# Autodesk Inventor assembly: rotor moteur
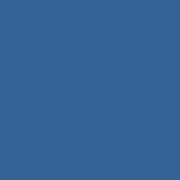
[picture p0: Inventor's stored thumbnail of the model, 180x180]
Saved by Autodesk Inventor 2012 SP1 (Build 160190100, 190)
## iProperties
Created: 2011-01
Part Number: rotor moteur
Document SubType Name: Assembly
Designer: eric
Mass: 15.8906 g
Surface Area: 104.881 cm^2
Volume: 15.8906 cm^3
Density: 1 g/cm^3
Author: eric
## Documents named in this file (5)
- D:\Cours\Inventor salle SI\chariot_de_golf_2008\chariot_de_golf_trolem\rotor moteur.iam
- D:\Cours\Inventor salle SI\chariot_de_golf_2008\chariot_de_golf_trolem\12Vis-sans-fin_Defaut.ipt
- D:\Cours\Inventor salle SI\chariot_de_golf_2008\chariot_de_golf_trolem\12manchon_accouplement_Defaut.ipt
- D:\Cours\Inventor salle SI\chariot_de_golf_2008\chariot_de_golf_trolem\12croix_elastique_Defaut.ipt
- D:\Cours\Inventor salle SI\chariot_de_golf_2008\chariot_de_golf_trolem\12axe_moteur_Defaut.ipt
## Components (5 placed, 4 different names)
1. 12Vis-sans-fin_Defaut:1
2. 12croix_elastique_Defaut:1
3. 12manchon_accouplement_Defaut:2
4. 12axe_moteur_Defaut:1
5. 12manchon_accouplement_Defaut:1
